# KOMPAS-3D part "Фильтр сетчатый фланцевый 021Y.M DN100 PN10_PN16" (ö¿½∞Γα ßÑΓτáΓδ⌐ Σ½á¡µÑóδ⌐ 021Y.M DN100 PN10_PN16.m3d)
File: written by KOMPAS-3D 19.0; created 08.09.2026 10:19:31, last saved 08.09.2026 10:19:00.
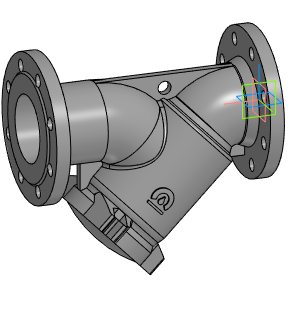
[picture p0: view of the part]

Document properties: Автор: Admin; Полное имя файла: Z:\3.Личные\sachek\Dendor\_3D для проектировщиков\8.2 Фильтр сетчатый 021Y.M\021Y.M_STP\Фильтр сетчатый фланцевый 021Y.M DN100 PN10_PN16.m3d

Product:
- Part/product: Фильтр сетчатый фланцевый 021Y.M DN100 PN10_PN16
    Масса: 24.1613

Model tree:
1. Операция без истории:1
